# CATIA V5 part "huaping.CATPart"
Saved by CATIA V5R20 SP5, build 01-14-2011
Part number: 花瓶
Bounding box of the stored display mesh (mm): x -24.597 to 24.597, y -24.614 to 24.589, z -40 to 60
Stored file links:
  E:\180211214wjl\huaping.CATPart
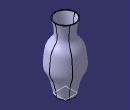
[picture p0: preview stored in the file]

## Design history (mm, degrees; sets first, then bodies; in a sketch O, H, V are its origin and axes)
Set1
  Plane1: type Offset, RefPlane xy-plane, Offset 20
  Plane2: type Offset, RefPlane Plane1, Offset 20
  Plane3: type Offset, RefPlane xy-plane, Offset 20, reversed
  Plane4: type Offset, RefPlane Plane3, Offset 20, reversed
  Plane5: type Offset, RefPlane Plane2, Offset 20
  Sketch1 on xy-plane, origin (0, 0, 0), H (1, 0, 0), V (0, 1, 0)
    circle A1 centre (0, 0) radius 24.6201
  Sketch2 on Plane3, origin (0, 0, -20), H (1, 0, 0), V (0, 1, 0)
    circle A1 centre (0, 0) radius 17.3982
  Sketch3 on Plane4, origin (0, 0, -40), H (1, 0, 0), V (0, 1, 0)
    circle A1 centre (0, 0) radius 12.9615
  Sketch4 on Plane1, origin (0, 0, 20), H (1, 0, 0), V (0, 1, 0)
    circle A1 centre (0, 0) radius 22.3514
  Sketch5 on Plane2, origin (0, 0, 40), H (1, 0, 0), V (0, 1, 0)
    circle A1 centre (0, 0) radius 0
    circle A2 centre (0, 0) radius 12.3414
  Sketch6 on Plane5, origin (0, 0, 60), H (1, 0, 0), V (0, 1, 0)
    circle A1 centre (0, 0) radius 15.6469
Body1 (main body)
  Loft1: solid, Sections (Sketch6; Sketch5; Sketch4; Sketch1; Sketch2; Sketch3)
  Shell1: ExtOffset 0, Face face of Loft1, IntOffset 1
